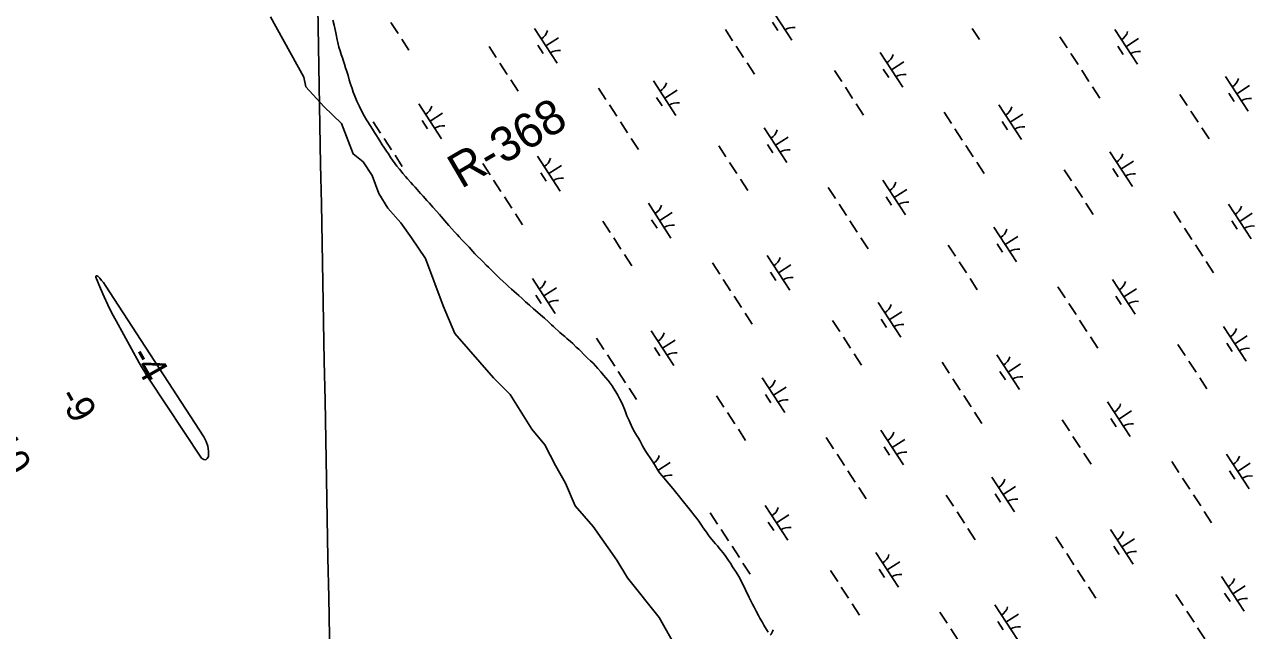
# Model space of a CAD drawing. Extents: x 3953924 to 3974542, y 193747 to 216192.
# Drawn here: x 3962117 to 3963597, y 206897 to 207626 of the extents above; entities that cross this region are included whole.
import ezdxf

# ---------------------------------------------------------------- set-up
doc = ezdxf.new("R2010")
doc.units = 0
for name, color, linetype in [('V-GRID-MAJR', 7, 'Continuous'), ('V-RIVR-EDGE', 7, 'Continuous'), ('V-RIVR-RANG', 7, 'Continuous'), ('V-RIVR-RANG-IDEN', 7, 'Continuous'), ('V-TOPO-MINR', 7, 'Continuous'), ('V-WETL-SWMP', 7, 'Continuous')]:
    doc.layers.add(name, color=color, linetype=linetype)

msp = doc.modelspace()

# ---------------------------------------------------------------- linework, layer by layer
at = {"layer": 'V-GRID-MAJR'}
msp.add_spline([(3962589.8, 201207.1), (3962493.7, 206368.6), (3962380.9, 212428.6), (3962369.3, 213053.2)], degree=3, dxfattribs=at)
at = {"layer": 'V-RIVR-EDGE'}
msp.add_lwpolyline([(3962413, 207635.4), (3962453.3, 207562.9), (3962455.7, 207551.1), (3962477.1, 207527.3), (3962498.5, 207507.1), (3962512.7, 207470.3), (3962524.6, 207460.8), (3962535.3, 207444.2), (3962543.6, 207422.8), (3962554.3, 207405), (3962569.7, 207387.2), (3962582.7, 207369.4), (3962599.4, 207344.5), (3962620.7, 207287.5), (3962635, 207254.3), (3962681.3, 207200.8), (3962701.5, 207180.7), (3962727.6, 207139.1), (3962743, 207120.1), (3962756.1, 207095.2), (3962768, 207073.8), (3962779.8, 207046.5), (3962801.2, 207021.6), (3962829.7, 206981.2), (3962842.7, 206959.8), (3962880.7, 206912.3), (3962902.1, 206874.3)], dxfattribs=at)
at = {"layer": 'V-TOPO-MINR'}
msp.add_lwpolyline([(3962337.6, 207118.4), (3962338.4, 207112.3), (3962338.5, 207106.1), (3962336.9, 207103.5), (3962335.1, 207102.1), (3962332.8, 207102.5), (3962330.2, 207104), (3962266.3, 207200.4), (3962263.4, 207204.9), (3962260.5, 207209.4), (3962257.8, 207214), (3962255.2, 207218.7), (3962227.4, 207269.2), (3962222.3, 207278.8), (3962217.4, 207288.5), (3962212.9, 207298.3), (3962208.6, 207308.2), (3962202.9, 207321.8), (3962203, 207322.8), (3962203.4, 207323.5), (3962204.2, 207323.6), (3962205.1, 207323.3), (3962207.5, 207320.8), (3962209.8, 207318.1), (3962211.9, 207315.4), (3962213.9, 207312.5), (3962332.7, 207129.6), (3962335.6, 207124.1), (3962337.6, 207118.4)], dxfattribs=at)
at = {"layer": 'V-WETL-SWMP'}
for p, q in [((3963013.2, 207649.1), (3963040.4, 207607.2)), ((3962487.9, 207631.4), (3962489.5, 207625.4)), ((3962489.5, 207625.4), (3962491.3, 207618.3)), ((3962491.3, 207618.3), (3962492, 207614.3)), ((3962557.8, 207628.8), (3962566.5, 207615.4)), ((3962730.9, 207621.4), (3962758.1, 207579.5)), ((3962960.4, 207620.1), (3962969.2, 207606.7)), ((3963017.1, 207629), (3963023.6, 207619)), ((3963257.4, 207621.4), (3963266.1, 207608)), ((3963428.9, 207620.3), (3963456.2, 207578.4)), ((3962492, 207614.3), (3962493.4, 207607.9)), ((3962493.4, 207607.9), (3962494.1, 207604.4)), ((3962494.1, 207604.4), (3962495.4, 207599.1)), ((3962570.9, 207608.7), (3962579.6, 207595.3)), ((3962744.5, 207600.4), (3962759.6, 207610.2)), ((3963363.1, 207611.4), (3963371.8, 207598)), ((3963442.5, 207599.4), (3963457.6, 207609.2)), ((3962495.4, 207599.1), (3962496.7, 207594.6)), ((3962496.7, 207594.6), (3962498.2, 207590)), ((3962498.2, 207590), (3962499.5, 207586.1)), ((3962676.1, 207599.7), (3962684.8, 207586.3)), ((3962734.8, 207601.2), (3962741.3, 207591.2)), ((3962973.5, 207600), (3962982.3, 207586.6)), ((3963146.6, 207592.5), (3963173.9, 207550.6)), ((3963376.1, 207591.3), (3963384.9, 207577.9)), ((3963432.8, 207600.2), (3963439.3, 207590.1)), ((3962499.5, 207586.1), (3962500.5, 207583.1)), ((3962500.5, 207583.1), (3962502, 207578.4)), ((3962502, 207578.4), (3962503.5, 207574.2)), ((3962503.5, 207574.2), (3962504.9, 207569.7)), ((3962689.2, 207579.6), (3962697.9, 207566.2)), ((3962986.6, 207579.9), (3962995.3, 207566.5)), ((3963150.5, 207572.4), (3963157, 207562.3)), ((3963160.2, 207571.6), (3963175.3, 207581.4)), ((3962504.9, 207569.7), (3962506.4, 207564.7)), ((3962506.4, 207564.7), (3962507.7, 207559.6)), ((3962507.7, 207559.6), (3962509, 207555.6)), ((3962702.3, 207559.5), (3962711, 207546)), ((3962873.8, 207558.4), (3962901, 207516.5)), ((3963091.8, 207570.8), (3963100.6, 207557.4)), ((3963389.2, 207571.2), (3963398, 207557.7)), ((3963562.3, 207563.7), (3963589.6, 207521.8)), ((3962509, 207555.6), (3962510.1, 207552.5)), ((3962510.1, 207552.5), (3962511.2, 207549.3)), ((3962511.2, 207549.3), (3962512.6, 207544.7)), ((3962512.6, 207544.7), (3962513.7, 207541.8)), ((3962807.9, 207549.5), (3962816.7, 207536.1)), ((3962887.4, 207537.4), (3962902.5, 207547.3)), ((3963104.9, 207550.7), (3963113.6, 207537.3)), ((3963402.3, 207551), (3963411.1, 207537.6)), ((3963566.2, 207543.6), (3963572.7, 207533.5)), ((3963575.9, 207542.7), (3963591, 207552.6)), ((3962513.7, 207541.8), (3962517.1, 207533.8)), ((3962517.1, 207533.8), (3962520, 207527.5)), ((3962591.5, 207530.6), (3962618.7, 207488.7)), ((3962821, 207529.4), (3962829.8, 207515.9)), ((3962877.7, 207538.3), (3962884.2, 207528.2)), ((3963118, 207530.6), (3963126.7, 207517.2)), ((3963289.5, 207529.6), (3963316.7, 207487.7)), ((3963507.5, 207542), (3963516.3, 207528.6)), ((3962520, 207527.5), (3962522.9, 207521.6)), ((3962522.9, 207521.6), (3962525.8, 207516.3)), ((3962525.8, 207516.3), (3962528.6, 207511.4)), ((3962605.1, 207509.7), (3962620.2, 207519.5)), ((3963223.6, 207520.6), (3963232.4, 207507.2)), ((3963303.1, 207508.6), (3963318.2, 207518.4)), ((3963520.6, 207521.9), (3963529.4, 207508.5)), ((3962528.6, 207511.4), (3962530.2, 207508.9)), ((3962530.2, 207508.9), (3962532.8, 207504.5)), ((3962532.8, 207504.5), (3962535.6, 207500.3)), ((3962535.6, 207500.3), (3962538.3, 207496)), ((3962536.7, 207508.9), (3962545.4, 207495.5)), ((3962595.4, 207510.5), (3962601.9, 207500.4)), ((3962834.1, 207509.2), (3962842.8, 207495.8)), ((3963007.2, 207501.8), (3963034.5, 207459.9)), ((3963236.7, 207500.5), (3963245.5, 207487.1)), ((3963293.4, 207509.4), (3963299.9, 207499.4)), ((3963533.7, 207501.8), (3963542.5, 207488.4)), ((3962538.3, 207496), (3962540.6, 207492.6)), ((3962540.6, 207492.6), (3962544.7, 207486.1)), ((3962544.7, 207486.1), (3962547.4, 207481.5)), ((3962549.8, 207488.8), (3962558.5, 207475.4)), ((3962847.2, 207489.1), (3962855.9, 207475.7)), ((3963020.8, 207480.8), (3963035.9, 207490.6)), ((3962547.4, 207481.5), (3962549.6, 207478.3)), ((3962549.6, 207478.3), (3962552.6, 207473.6)), ((3962552.6, 207473.6), (3962554.9, 207470.4)), ((3962554.9, 207470.4), (3962557.9, 207465.7)), ((3962952.4, 207480.1), (3962961.1, 207466.7)), ((3963011.1, 207481.6), (3963017.6, 207471.6)), ((3963249.8, 207480.4), (3963258.6, 207467)), ((3963422.9, 207472.9), (3963450.2, 207431)), ((3962557.9, 207465.7), (3962559.9, 207462.8)), ((3962559.9, 207462.8), (3962563.1, 207458.6)), ((3962562.9, 207468.7), (3962571.6, 207455.3)), ((3962563.1, 207458.6), (3962565.1, 207455.8)), ((3962565.1, 207455.8), (3962568.1, 207452.1)), ((3962668.5, 207458.7), (3962677.3, 207445.3)), ((3962734.3, 207467.7), (3962761.6, 207425.7)), ((3962748, 207446.7), (3962763.1, 207456.5)), ((3962965.5, 207460), (3962974.2, 207446.6)), ((3963262.9, 207460.3), (3963271.7, 207446.9)), ((3963436.5, 207452), (3963451.6, 207461.8)), ((3962568.1, 207452.1), (3962570.1, 207449.4)), ((3962570.1, 207449.4), (3962572.4, 207446.9)), ((3962572.4, 207446.9), (3962575.5, 207443)), ((3962575.5, 207443), (3962577.8, 207440.5)), ((3962577.8, 207440.5), (3962581.9, 207436.1)), ((3962738.2, 207447.5), (3962744.8, 207437.5)), ((3962978.6, 207439.9), (3962987.3, 207426.5)), ((3963368.1, 207451.3), (3963376.9, 207437.9)), ((3963426.8, 207452.8), (3963433.3, 207442.8)), ((3962581.9, 207436.1), (3962584.4, 207433.3)), ((3962584.4, 207433.3), (3962587, 207430.2)), ((3962587, 207430.2), (3962589.6, 207427.6)), ((3962589.6, 207427.6), (3962593.7, 207422.8)), ((3962681.6, 207438.6), (3962690.4, 207425.2)), ((3963084.2, 207429.9), (3963093, 207416.5)), ((3963150.1, 207438.8), (3963177.3, 207396.9)), ((3963163.7, 207417.9), (3963178.8, 207427.7)), ((3963381.2, 207431.2), (3963390, 207417.7)), ((3962593.7, 207422.8), (3962596.7, 207419.3)), ((3962596.7, 207419.3), (3962601.3, 207414.2)), ((3962601.3, 207414.2), (3962604.3, 207411)), ((3962604.3, 207411), (3962608.4, 207406.4)), ((3962694.7, 207418.5), (3962703.4, 207405.1)), ((3962867.8, 207411), (3962895, 207369.1)), ((3963097.3, 207409.8), (3963106.1, 207396.4)), ((3963154, 207418.7), (3963160.5, 207408.6)), ((3963394.3, 207411), (3963403, 207397.6)), ((3963565.8, 207410), (3963593.1, 207368.1)), ((3962608.4, 207406.4), (3962613.3, 207401.1)), ((3962613.3, 207401.1), (3962616.3, 207397.3)), ((3962616.3, 207397.3), (3962618.4, 207395)), ((3962618.4, 207395), (3962623, 207389.6)), ((3962707.8, 207398.4), (3962716.5, 207385)), ((3962881.4, 207390.1), (3962896.5, 207399.9)), ((3963500, 207401.1), (3963508.7, 207387.6)), ((3963579.4, 207389), (3963594.5, 207398.9)), ((3962623, 207389.6), (3962625.4, 207386.8)), ((3962625.4, 207386.8), (3962627.7, 207384.1)), ((3962627.7, 207384.1), (3962631.3, 207380.3)), ((3962631.3, 207380.3), (3962634.6, 207376.6)), ((3962813, 207389.4), (3962821.7, 207375.9)), ((3962871.7, 207390.9), (3962878.2, 207380.8)), ((3963110.4, 207389.7), (3963119.2, 207376.3)), ((3963283.5, 207382.2), (3963310.8, 207340.3)), ((3963513.1, 207380.9), (3963521.8, 207367.5)), ((3963569.7, 207389.9), (3963576.2, 207379.8)), ((3962634.6, 207376.6), (3962637.6, 207373.2)), ((3962637.6, 207373.2), (3962640.2, 207370.5)), ((3962640.2, 207370.5), (3962643.4, 207367.1)), ((3962643.4, 207367.1), (3962647.5, 207362.9)), ((3962826.1, 207369.2), (3962834.8, 207355.8)), ((3963123.5, 207369.5), (3963132.3, 207356.1)), ((3963297.1, 207361.3), (3963312.2, 207371.1)), ((3962647.5, 207362.9), (3962652.1, 207357.9)), ((3962652.1, 207357.9), (3962656.6, 207352.9)), ((3962656.6, 207352.9), (3962659.1, 207350.1)), ((3963228.7, 207360.5), (3963237.5, 207347.1)), ((3963287.4, 207362.1), (3963293.9, 207352)), ((3963526.1, 207360.8), (3963534.9, 207347.4)), ((3962659.1, 207350.1), (3962669.2, 207339.9)), ((3962669.2, 207339.9), (3962672.7, 207336.6)), ((3962672.7, 207336.6), (3962675.4, 207333.8)), ((3962839.2, 207349.1), (3962847.9, 207335.7)), ((3962944.8, 207339.1), (3962953.6, 207325.7)), ((3963010.7, 207348.1), (3963037.9, 207306.2)), ((3963024.3, 207327.1), (3963039.4, 207336.9)), ((3963241.8, 207340.4), (3963250.6, 207327)), ((3963539.2, 207340.7), (3963548, 207327.3)), ((3962675.4, 207333.8), (3962678.5, 207330.6)), ((3962678.5, 207330.6), (3962681.2, 207328.2)), ((3962681.2, 207328.2), (3962685, 207324.5)), ((3962685, 207324.5), (3962689.1, 207320.4)), ((3963014.6, 207327.9), (3963021.1, 207317.9)), ((3962689.1, 207320.4), (3962693.2, 207316.6)), ((3962693.2, 207316.6), (3962696.6, 207313.4)), ((3962696.6, 207313.4), (3962699.5, 207310.7)), ((3962699.5, 207310.7), (3962702.9, 207307.5)), ((3962702.9, 207307.5), (3962705.8, 207304.9)), ((3962728.4, 207320.3), (3962755.6, 207278.4)), ((3962742, 207299.3), (3962757.1, 207309.2)), ((3962957.9, 207319), (3962966.7, 207305.6)), ((3963254.9, 207320.3), (3963263.6, 207306.9)), ((3963360.6, 207310.3), (3963369.3, 207296.9)), ((3963426.4, 207319.2), (3963453.7, 207277.3)), ((3963440, 207298.3), (3963455.1, 207308.1)), ((3962705.8, 207304.9), (3962709, 207302.3)), ((3962709, 207302.3), (3962711.7, 207299.7)), ((3962711.7, 207299.7), (3962715.7, 207296.4)), ((3962715.7, 207296.4), (3962720.1, 207292.3)), ((3962720.1, 207292.3), (3962724.9, 207288.1)), ((3962732.3, 207300.2), (3962738.8, 207290.1)), ((3962971, 207298.9), (3962979.8, 207285.5)), ((3963144.1, 207291.5), (3963171.4, 207249.6)), ((3963430.3, 207299.1), (3963436.8, 207289.1)), ((3962724.9, 207288.1), (3962729.6, 207283.9)), ((3962729.6, 207283.9), (3962734.7, 207279.4)), ((3962734.7, 207279.4), (3962737.9, 207276.6)), ((3962737.9, 207276.6), (3962742.6, 207272.5)), ((3962984.1, 207278.8), (3962992.8, 207265.4)), ((3963157.7, 207270.5), (3963172.8, 207280.3)), ((3963373.6, 207290.2), (3963382.4, 207276.8)), ((3962742.6, 207272.5), (3962747.4, 207268.2)), ((3962747.4, 207268.2), (3962751.3, 207264.6)), ((3962751.3, 207264.6), (3962753.8, 207262.4)), ((3962753.8, 207262.4), (3962761.4, 207255.4)), ((3963089.3, 207269.8), (3963098.1, 207256.4)), ((3963148, 207271.3), (3963154.5, 207261.3)), ((3963386.7, 207270.1), (3963395.5, 207256.7)), ((3963559.8, 207262.6), (3963587.1, 207220.7)), ((3962761.4, 207255.4), (3962763.8, 207253.5)), ((3962763.8, 207253.5), (3962767.3, 207250.4)), ((3962767.3, 207250.4), (3962769.7, 207248.1)), ((3962769.7, 207248.1), (3962773.9, 207244.4)), ((3962805.4, 207248.4), (3962814.2, 207235)), ((3962871.3, 207257.3), (3962898.5, 207215.4)), ((3963102.4, 207249.7), (3963111.1, 207236.3)), ((3963399.8, 207250), (3963408.6, 207236.6)), ((3963573.4, 207241.7), (3963588.5, 207251.5)), ((3962773.9, 207244.4), (3962776.7, 207241.9)), ((3962776.7, 207241.9), (3962781, 207237.8)), ((3962781, 207237.8), (3962783.9, 207235.1)), ((3962783.9, 207235.1), (3962786.4, 207232.7)), ((3962786.4, 207232.7), (3962789.9, 207229.3)), ((3962875.2, 207237.2), (3962881.7, 207227.1)), ((3962884.9, 207236.4), (3962900, 207246.2)), ((3963505, 207241), (3963513.8, 207227.5)), ((3963563.7, 207242.5), (3963570.2, 207232.4)), ((3962789.9, 207229.3), (3962792.2, 207226.8)), ((3962792.2, 207226.8), (3962794.6, 207224.5)), ((3962794.6, 207224.5), (3962798.3, 207221.4)), ((3962798.3, 207221.4), (3962801.4, 207218.2)), ((3962801.4, 207218.2), (3962804.2, 207215)), ((3962818.5, 207228.3), (3962827.3, 207214.9)), ((3963115.5, 207229.6), (3963124.2, 207216.1)), ((3963221.2, 207219.6), (3963229.9, 207206.2)), ((3963287, 207228.5), (3963314.2, 207186.6)), ((3963300.6, 207207.5), (3963315.7, 207217.4)), ((3963518.1, 207220.8), (3963526.9, 207207.4)), ((3962804.2, 207215), (3962807.1, 207211.8)), ((3962807.1, 207211.8), (3962810.4, 207208)), ((3962810.4, 207208), (3962813.9, 207204)), ((3962813.9, 207204), (3962816.6, 207200.8)), ((3962831.6, 207208.2), (3962840.4, 207194.8)), ((3963290.9, 207208.4), (3963297.4, 207198.3)), ((3962816.6, 207200.8), (3962819.2, 207197.4)), ((3962819.2, 207197.4), (3962821.6, 207194.2)), ((3962821.6, 207194.2), (3962824.1, 207190.9)), ((3962824.1, 207190.9), (3962825.9, 207188.1)), ((3962825.9, 207188.1), (3962828.5, 207184)), ((3962844.7, 207188.1), (3962853.4, 207174.6)), ((3963004.7, 207200.7), (3963032, 207158.8)), ((3963018.3, 207179.8), (3963033.4, 207189.6)), ((3963234.2, 207199.5), (3963243, 207186)), ((3963531.2, 207200.7), (3963540, 207187.3)), ((3962828.5, 207184), (3962831.1, 207179.8)), ((3962831.1, 207179.8), (3962833.6, 207175.2)), ((3962833.6, 207175.2), (3962835, 207172.4)), ((3962949.9, 207179), (3962958.7, 207165.6)), ((3963008.6, 207180.6), (3963015.1, 207170.5)), ((3963247.3, 207179.3), (3963256.1, 207165.9)), ((3962835, 207172.4), (3962837, 207167.9)), ((3962837, 207167.9), (3962839, 207162.8)), ((3962839, 207162.8), (3962840.6, 207158.5)), ((3962840.6, 207158.5), (3962842, 207155)), ((3962963, 207158.9), (3962971.7, 207145.5)), ((3963260.4, 207159.2), (3963269.2, 207145.8)), ((3963420.4, 207171.9), (3963447.7, 207130)), ((3963434, 207150.9), (3963449.1, 207160.8)), ((3962842, 207155), (3962844.5, 207149.4)), ((3962844.5, 207149.4), (3962847, 207143.6)), ((3962847, 207143.6), (3962850, 207137.8)), ((3963365.6, 207150.2), (3963374.4, 207136.8)), ((3963424.3, 207151.8), (3963430.8, 207141.7)), ((3962850, 207137.8), (3962853.5, 207131.7)), ((3962853.5, 207131.7), (3962855.7, 207127.9)), ((3962976.1, 207138.8), (3962984.8, 207125.4)), ((3963081.7, 207128.8), (3963090.5, 207115.4)), ((3963147.6, 207137.8), (3963174.8, 207095.9)), ((3963378.7, 207130.1), (3963387.5, 207116.7)), ((3962855.7, 207127.9), (3962857.3, 207125.2)), ((3962857.3, 207125.2), (3962859.4, 207121.4)), ((3962859.4, 207121.4), (3962860.8, 207118.8)), ((3962860.8, 207118.8), (3962862.3, 207116.1)), ((3962862.3, 207116.1), (3962864.7, 207112.1)), ((3963151.5, 207117.6), (3963158, 207107.6)), ((3963161.2, 207116.8), (3963176.3, 207126.6)), ((3962864.7, 207112.1), (3962866.4, 207109.6)), ((3962866.4, 207109.6), (3962870.6, 207103.1)), ((3962870.6, 207103.1), (3962873, 207099.4)), ((3962873, 207099.4), (3962876.2, 207094.2)), ((3962879.3, 207089.2), (3962894, 207098.8)), ((3963094.8, 207108.7), (3963103.6, 207095.3)), ((3963391.8, 207110), (3963400.6, 207096.6)), ((3963497.5, 207100), (3963506.2, 207086.6)), ((3963563.3, 207108.9), (3963590.6, 207067)), ((3962876.2, 207094.2), (3962879.1, 207089.5)), ((3962879.1, 207089.5), (3962881.7, 207086)), ((3962881.7, 207086), (3962884.5, 207082.7)), ((3963107.9, 207088.6), (3963116.7, 207075.2)), ((3963567.2, 207088.8), (3963573.7, 207078.7)), ((3963576.9, 207088), (3963592, 207097.8)), ((3962884.5, 207082.7), (3962892.7, 207072.8)), ((3962892.7, 207072.8), (3962897.1, 207067.3)), ((3963281, 207081.1), (3963308.3, 207039.2)), ((3963294.6, 207060.2), (3963309.7, 207070)), ((3963510.6, 207079.9), (3963519.3, 207066.5)), ((3962897.1, 207067.3), (3962901.9, 207061.4)), ((3962901.9, 207061.4), (3962903.9, 207059)), ((3962903.9, 207059), (3962908.6, 207053.3)), ((3963121, 207068.5), (3963129.8, 207055.1)), ((3963226.2, 207059.5), (3963235, 207046.1)), ((3963284.9, 207061), (3963291.4, 207051)), ((3963523.6, 207059.8), (3963532.4, 207046.4)), ((3962908.6, 207053.3), (3962911.5, 207049.6)), ((3962911.5, 207049.6), (3962913.5, 207047)), ((3962913.5, 207047), (3962916.8, 207043)), ((3962916.8, 207043), (3962920.2, 207038.8)), ((3963008.2, 207047), (3963035.4, 207005.1)), ((3963536.7, 207039.7), (3963545.5, 207026.2)), ((3962920.2, 207038.8), (3962922.5, 207035.8)), ((3962922.5, 207035.8), (3962926, 207031.4)), ((3962926, 207031.4), (3962928.3, 207028.2)), ((3962928.3, 207028.2), (3962931.7, 207023.3)), ((3962942.3, 207038.1), (3962951.1, 207024.7)), ((3963012.1, 207026.9), (3963018.6, 207016.8)), ((3963021.8, 207026.1), (3963036.9, 207035.9)), ((3963239.3, 207039.3), (3963248.1, 207025.9)), ((3962931.7, 207023.3), (3962933.9, 207019.9)), ((3962933.9, 207019.9), (3962937.6, 207014.8)), ((3962937.6, 207014.8), (3962939.9, 207011.6)), ((3962939.9, 207011.6), (3962942.2, 207008.3)), ((3962955.4, 207018), (3962964.2, 207004.6)), ((3963252.4, 207019.2), (3963261.1, 207005.8)), ((3963423.9, 207018.2), (3963451.2, 206976.3)), ((3962942.2, 207008.3), (3962946.2, 207003.6)), ((3962946.2, 207003.6), (3962948.4, 207000.9)), ((3962948.4, 207000.9), (3962951, 206998.3)), ((3962951, 206998.3), (3962952.8, 206995.7)), ((3962952.8, 206995.7), (3962954.9, 206993.4)), ((3962968.5, 206997.9), (3962977.3, 206984.4)), ((3963358.1, 207009.2), (3963366.8, 206995.8)), ((3963427.8, 206998), (3963434.3, 206988)), ((3963437.5, 206997.2), (3963452.6, 207007)), ((3962954.9, 206993.4), (3962957.6, 206989.8)), ((3962957.6, 206989.8), (3962960.9, 206985.5)), ((3962960.9, 206985.5), (3962964.3, 206980.7)), ((3962964.3, 206980.7), (3962966.5, 206977.5)), ((3963141.6, 206990.4), (3963168.9, 206948.5)), ((3963371.2, 206989.1), (3963379.9, 206975.7)), ((3962966.5, 206977.5), (3962969.2, 206973.3)), ((3962969.2, 206973.3), (3962973.4, 206966.8)), ((3962973.4, 206966.8), (3962976.5, 206961.3)), ((3962981.6, 206977.7), (3962990.4, 206964.3)), ((3963086.8, 206968.7), (3963095.6, 206955.3)), ((3963145.5, 206970.3), (3963152, 206960.2)), ((3963155.2, 206969.4), (3963170.3, 206979.3)), ((3963384.2, 206969), (3963393, 206955.6)), ((3962976.5, 206961.3), (3962978.5, 206957.8)), ((3962978.5, 206957.8), (3962980.8, 206953.3)), ((3962980.8, 206953.3), (3962983.8, 206947.3)), ((3963557.3, 206961.6), (3963584.6, 206919.7)), ((3962983.8, 206947.3), (3962985.6, 206943.4)), ((3962985.6, 206943.4), (3962987.1, 206940.7)), ((3962987.1, 206940.7), (3962989.2, 206936.1)), ((3962989.2, 206936.1), (3962990.7, 206932.9)), ((3963099.9, 206948.6), (3963108.7, 206935.2)), ((3963397.3, 206948.9), (3963406.1, 206935.5)), ((3963502.5, 206939.9), (3963511.3, 206926.5)), ((3963561.2, 206941.4), (3963567.7, 206931.4)), ((3963570.9, 206940.6), (3963586, 206950.4)), ((3962990.7, 206932.9), (3962993.2, 206928.1)), ((3962993.2, 206928.1), (3962994.9, 206924.7)), ((3962994.9, 206924.7), (3962997.4, 206919.7)), ((3963113, 206928.5), (3963121.7, 206915.1)), ((3963284.5, 206927.4), (3963311.8, 206885.5)), ((3962997.4, 206919.7), (3963000.1, 206914.6)), ((3963000.1, 206914.6), (3963002, 206911.2)), ((3963002, 206911.2), (3963005.1, 206906)), ((3963218.7, 206918.5), (3963227.4, 206905.1)), ((3963288.4, 206907.3), (3963294.9, 206897.2)), ((3963298.1, 206906.5), (3963313.2, 206916.3)), ((3963515.6, 206919.8), (3963524.4, 206906.4)), ((3963005.1, 206906), (3963006.8, 206902.8)), ((3963006.8, 206902.8), (3963009.8, 206897.7)), ((3963009.8, 206897.7), (3963012, 206894.3)), ((3963231.7, 206898.4), (3963240.5, 206885)), ((3963528.7, 206899.7), (3963537.5, 206886.3))]:
    msp.add_line(p, q, dxfattribs=at)
for centre, start, end in [((3962729.6, 207623.7), 302.2901, 343.8338), ((3963042.1, 207605.2), 82.2901, 123.8337), ((3963427.6, 207622.6), 302.2901, 343.8338), ((3962759.8, 207577.4), 82.2901, 123.8337), ((3963145.3, 207594.9), 302.2901, 343.8338), ((3963457.8, 207576.3), 82.2901, 123.8337), ((3963175.5, 207548.6), 82.2901, 123.8337), ((3963561.1, 207566), 302.2901, 343.8338), ((3962872.5, 207560.7), 302.2901, 343.8338), ((3962590.2, 207532.9), 302.2901, 343.8338), ((3962902.7, 207514.4), 82.2901, 123.8337), ((3963591.2, 207519.7), 82.2901, 123.8337), ((3963288.2, 207531.9), 302.2901, 343.8338), ((3962620.4, 207486.6), 82.2901, 123.8337), ((3963005.9, 207504.1), 302.2901, 343.8338), ((3963318.4, 207485.6), 82.2901, 123.8337), ((3963036.1, 207457.8), 82.2901, 123.8337), ((3963421.7, 207475.3), 302.2901, 343.8338), ((3962733.1, 207470), 302.2901, 343.8338), ((3962763.3, 207423.7), 82.2901, 123.8337), ((3963451.8, 207429), 82.2901, 123.8337), ((3963148.8, 207441.1), 302.2901, 343.8338), ((3963179, 207394.8), 82.2901, 123.8337), ((3962866.5, 207413.4), 302.2901, 343.8338), ((3963564.5, 207412.3), 302.2901, 343.8338), ((3962896.7, 207367.1), 82.2901, 123.8337), ((3963594.7, 207366), 82.2901, 123.8337), ((3963282.3, 207384.5), 302.2901, 343.8338), ((3963312.4, 207338.2), 82.2901, 123.8337), ((3963009.4, 207350.4), 302.2901, 343.8338), ((3963039.6, 207304.1), 82.2901, 123.8337), ((3962727.1, 207322.6), 302.2901, 343.8338), ((3963425.1, 207321.6), 302.2901, 343.8338), ((3962757.3, 207276.3), 82.2901, 123.8337), ((3963455.3, 207275.3), 82.2901, 123.8337), ((3963142.9, 207293.8), 302.2901, 343.8338), ((3963173, 207247.5), 82.2901, 123.8337), ((3962870, 207259.7), 302.2901, 343.8338), ((3963558.6, 207265), 302.2901, 343.8338), ((3963588.7, 207218.7), 82.2901, 123.8337), ((3962900.2, 207213.4), 82.2901, 123.8337), ((3963285.7, 207230.8), 302.2901, 343.8338), ((3963003.4, 207203), 302.2901, 343.8338), ((3963315.9, 207184.5), 82.2901, 123.8337), ((3963033.6, 207156.7), 82.2901, 123.8337), ((3963419.2, 207174.2), 302.2901, 343.8338), ((3963449.3, 207127.9), 82.2901, 123.8337), ((3963146.3, 207140.1), 302.2901, 343.8338), ((3962864, 207112.3), 304.4937, 343.8338), ((3963176.5, 207093.8), 82.2901, 123.8337), ((3963562.1, 207111.3), 302.2901, 343.8338), ((3962894.2, 207066), 82.2901, 119.1358), ((3963279.8, 207083.5), 302.2901, 343.8338), ((3963592.2, 207065), 82.2901, 123.8337), ((3963309.9, 207037.2), 82.2901, 123.8337), ((3963006.9, 207049.3), 302.2901, 343.8338), ((3963037.1, 207003), 82.2901, 123.8337), ((3963422.6, 207020.5), 302.2901, 343.8338), ((3963140.4, 206992.7), 302.2901, 343.8338), ((3963452.8, 206974.2), 82.2901, 123.8337), ((3963170.5, 206946.4), 82.2901, 123.8337), ((3963556.1, 206963.9), 302.2901, 343.8338), ((3963283.2, 206929.8), 302.2901, 343.8338), ((3963586.2, 206917.6), 82.2901, 123.8337), ((3963000.9, 206902), 319.9514, 343.8338), ((3963313.4, 206883.5), 82.2901, 123.8337)]:
    msp.add_arc(centre, 17.6, start, end, dxfattribs=at)

# ---------------------------------------------------------------- texts
at = {"layer": 'V-RIVR-RANG'}
for s, p in [('-4', (3962242.9, 207227.6)), ('-9', (3962156.8, 207178.4)), ('-10', (3962065.9, 207135.9))]:
    msp.add_text(s, height=33.5, rotation=299.7323, dxfattribs=at).set_placement(p)
at = {"layer": 'V-RIVR-RANG-IDEN'}
msp.add_text('R-368  ', height=41.5, rotation=30.2778, dxfattribs=at).set_placement((3962642.5, 207427.8))

doc.saveas('drawing.dxf')
